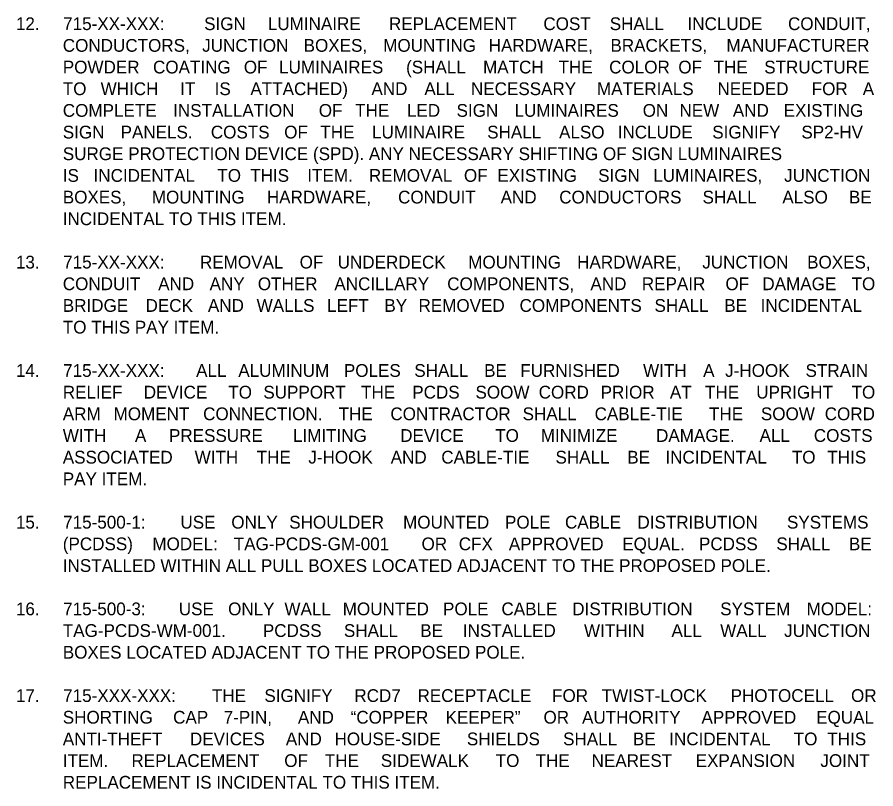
# Model space of a CAD drawing. Extents: x -55 to 2471539, y -90 to 3608906.
# Drawn here: x 543.9 to 1015.2, y 2948.6 to 3372.3 of the extents above; entities that cross this region are included whole.
import ezdxf

# ---------------------------------------------------------------- set-up
doc = ezdxf.new("R2010")
doc.units = 0
doc.layers.add('XSCell', color=7, linetype='Continuous')

msp = doc.modelspace()

# ---------------------------------------------------------------- texts
at = {"layer": 'XSCell'}
for s, p in [('12.', (543.22, 3365.2)), ('715-XX-XXX: ', (569.17, 3365.2)), ('SIGN ', (646.54, 3365.2)), ('LUMINAIRE ', (681.53, 3365.2)), ('REPLACEMENT ', (747.98, 3365.2)), ('COST ', (832.73, 3365.2)), ('SHALL ', (869.16, 3365.2)), ('INCLUDE ', (911.86, 3365.2)), ('CONDUIT, ', (967.01, 3365.2)), ('CONDUCTORS, ', (568.97, 3353.3)), ('JUNCTION ', (645.47, 3353.3)), ('BOXES, ', (701.16, 3353.3)), ('MOUNTING ', (744.83, 3353.3)), ('HARDWARE, ', (802.74, 3353.3)), ('BRACKETS, ', (869.55, 3353.3)), ('MANUFACTURER ', (933.2, 3353.3)), ('POWDER ', (568.97, 3341.4)), ('COATING ', (618.49, 3341.4)), ('OF ', (668.33, 3341.4)), ('LUMINAIRES ', (687.66, 3341.4)), ('(SHALL ', (757.39, 3341.4)), ('MATCH ', (799.64, 3341.4)), ('THE ', (841.03, 3341.4)), ('COLOR ', (868.85, 3341.4)), ('OF ', (906.81, 3341.4)), ('THE ', (926.14, 3341.4)), ('STRUCTURE ', (953.96, 3341.4)), ('ATTACHED) ', (671.94, 3329.5)), ('TO ', (568.97, 3329.5)), ('WHICH ', (589.74, 3329.5)), ('IT ', (633.36, 3329.5)), ('IS ', (652.3, 3329.5)), ('AND ', (738.36, 3329.5)), ('ALL ', (767.43, 3329.5)), ('NECESSARY ', (792.98, 3329.5)), ('MATERIALS ', (862.16, 3329.5)), ('NEEDED ', (928.29, 3329.5)), ('FOR ', (980.04, 3329.5)), ('A ', (1008.04, 3329.5)), ('COMPLETE ', (568.97, 3317.6)), ('INSTALLATION ', (629.54, 3317.6)), ('OF ', (709.47, 3317.6)), ('THE ', (729.42, 3317.6)), ('LED ', (757.86, 3317.6)), ('SIGN ', (785.1, 3317.6)), ('LUMINAIRES ', (816.92, 3317.6)), ('ON ', (887.26, 3317.6)), ('NEW ', (907.43, 3317.6)), ('AND ', (936.73, 3317.6)), ('EXISTING ', (964.63, 3317.6)), ('SIGN ', (568.97, 3305.7)), ('PANELS. ', (600.71, 3305.7)), ('COSTS ', (650.23, 3305.7)), ('OF ', (690.48, 3305.7)), ('THE ', (710.35, 3305.7)), ('LUMINAIRE ', (738.71, 3305.7)), ('SHALL ', (801.9, 3305.7)), ('ALSO ', (841.35, 3305.7)), ('INCLUDE ', (873.54, 3305.7)), ('SIGNIFY ', (925.43, 3305.7)), ('SP2-HV ', (974.35, 3305.7)), ('SURGE PROTECTION DEVICE (SPD). ANY NECESSARY SHIFTING OF SIGN LUMINAIRES ', (568.97, 3293.8)), ('IS ', (568.97, 3281.9)), ('INCIDENTAL ', (585.86, 3281.9)), ('TO ', (653.79, 3281.9)), ('THIS ', (671.82, 3281.9)), ('ITEM. ', (703.16, 3281.9)), ('REMOVAL ', (736.96, 3281.9)), ('OF ', (789.14, 3281.9)), ('EXISTING ', (807.51, 3281.9)), ('SIGN ', (862.81, 3281.9)), ('LUMINAIRES, ', (893.05, 3281.9)), ('JUNCTION ', (964.88, 3281.9)), ('BOXES, ', (568.97, 3270)), ('MOUNTING ', (617.84, 3270)), ('HARDWARE, ', (680.97, 3270)), ('CONDUIT ', (752.99, 3270)), ('AND ', (809.28, 3270)), ('CONDUCTORS ', (841.45, 3270)), ('SHALL ', (920.11, 3270)), ('ALSO ', (963.9, 3270)), ('BE ', (1000.44, 3270)), ('INCIDENTAL TO THIS ITEM.', (568.97, 3258.1)), ('13.', (543.22, 3234.3)), ('715-XX-XXX: ', (569.17, 3234.3)), ('REMOVAL ', (644.27, 3234.3)), ('OF ', (698.96, 3234.3)), ('UNDERDECK ', (719.83, 3234.3)), ('MOUNTING ', (791.49, 3234.3)), ('HARDWARE, ', (851.27, 3234.3)), ('JUNCTION ', (919.94, 3234.3)), ('BOXES, ', (977.5, 3234.3)), ('CONDUIT ', (568.97, 3222.4)), ('AND ', (621.32, 3222.4)), ('ANY ', (649.54, 3222.4)), ('OTHER ', (676.01, 3222.4)), ('ANCILLARY ', (718.01, 3222.4)), ('COMPONENTS, ', (779.96, 3222.4)), ('AND ', (858.56, 3222.4)), ('REPAIR ', (886.78, 3222.4)), ('OF ', (932.66, 3222.4)), ('DAMAGE ', (952.93, 3222.4)), ('TO ', (1001.9, 3222.4)), ('BRIDGE ', (568.97, 3210.5)), ('DECK ', (614.38, 3210.5)), ('AND ', (648.62, 3210.5)), ('WALLS ', (675.36, 3210.5)), ('LEFT ', (714.01, 3210.5)), ('BY ', (745.49, 3210.5)), ('REMOVED ', (764.2, 3210.5)), ('COMPONENTS ', (819.66, 3210.5)), ('SHALL ', (893.72, 3210.5)), ('BE ', (932.08, 3210.5)), ('INCIDENTAL ', (951.99, 3210.5)), ('TO THIS PAY ITEM.', (568.97, 3198.6)), ('14.', (543.22, 3174.8)), ('715-XX-XXX: ', (569.17, 3174.8)), ('ALL ', (642.14, 3174.8)), ('ALUMINUM ', (665.3, 3174.8)), ('POLES ', (723.25, 3174.8)), ('SHALL ', (761.9, 3174.8)), ('BE ', (800.21, 3174.8)), ('FURNISHED ', (820.07, 3174.8)), ('WITH ', (887.46, 3174.8)), ('A ', (920.44, 3174.8)), ('J-HOOK ', (932.51, 3174.8)), ('STRAIN ', (976.64, 3174.8)), ('RELIEF ', (568.97, 3162.9)), ('DEVICE ', (613.41, 3162.9)), ('TO ', (659.8, 3162.9)), ('SUPPORT ', (679.05, 3162.9)), ('THE ', (732.69, 3162.9)), ('PCDS ', (760.78, 3162.9)), ('SOOW ', (795.48, 3162.9)), ('CORD ', (830.16, 3162.9)), ('PRIOR ', (864.16, 3162.9)), ('AT ', (902.18, 3162.9)), ('THE ', (921.48, 3162.9)), ('UPRIGHT ', (949.56, 3162.9)), ('TO ', (1001.9, 3162.9)), ('ARM ', (568.97, 3151)), ('MOMENT ', (596.85, 3151)), ('CONNECTION. ', (645.98, 3151)), ('THE ', (720.32, 3151)), ('CONTRACTOR ', (748.76, 3151)), ('SHALL ', (821.34, 3151)), ('CABLE-TIE ', (860.87, 3151)), ('THE ', (923.67, 3151)), ('SOOW ', (952.12, 3151)), ('CORD ', (987.15, 3151)), ('WITH ', (568.97, 3139.1)), ('A ', (608.57, 3139.1)), ('PRESSURE ', (627.26, 3139.1)), ('LIMITING ', (695.29, 3139.1)), ('DEVICE ', (754.15, 3139.1)), ('TO ', (806.3, 3139.1)), ('MINIMIZE ', (831.32, 3139.1)), ('DAMAGE. ', (894.58, 3139.1)), ('ALL ', (951.4, 3139.1)), ('COSTS ', (981.18, 3139.1)), ('ASSOCIATED ', (568.97, 3127.2)), ('WITH ', (641.34, 3127.2)), ('THE ', (675.41, 3127.2)), ('J-HOOK ', (703.72, 3127.2)), ('AND ', (748.94, 3127.2)), ('CABLE-TIE ', (776.71, 3127.2)), ('SHALL ', (839.39, 3127.2)), ('BE ', (878.78, 3127.2)), ('INCIDENTAL ', (899.73, 3127.2)), ('TO ', (969.12, 3127.2)), ('THIS ', (988.6, 3127.2)), ('PAY ITEM.', (568.97, 3115.3)), ('15.', (543.22, 3091.5)), ('715-500-1: ', (569.17, 3091.5)), ('USE ', (633.53, 3091.5)), ('ONLY ', (661.46, 3091.5)), ('SHOULDER ', (693.26, 3091.5)), ('MOUNTED ', (755.74, 3091.5)), ('POLE ', (811.69, 3091.5)), ('CABLE ', (844.61, 3091.5)), ('DISTRIBUTION ', (884.36, 3091.5)), ('SYSTEMS ', (966.44, 3091.5)), ('(PCDSS) ', (568.97, 3079.6)), ('MODEL: ', (618.13, 3079.6)), ('TAG-PCDS-GM-001 ', (662.81, 3079.6)), ('OR ', (765.87, 3079.6)), ('CFX ', (786.3, 3079.6)), ('APPROVED ', (813.79, 3079.6)), ('EQUAL. ', (876.02, 3079.6)), ('PCDSS ', (918.14, 3079.6)), ('SHALL ', (960.6, 3079.6)), ('BE ', (1000.44, 3079.6)), ('INSTALLED WITHIN ALL PULL BOXES LOCATED ADJACENT TO THE PROPOSED POLE.', (568.97, 3067.7)), ('16.', (543.22, 3043.9)), ('715-500-3: ', (569.17, 3043.9)), ('USE ', (632.65, 3043.9)), ('ONLY ', (659.7, 3043.9)), ('WALL ', (690.61, 3043.9)), ('MOUNTED ', (722.61, 3043.9)), ('POLE ', (777.67, 3043.9)), ('CABLE ', (809.72, 3043.9)), ('DISTRIBUTION ', (848.58, 3043.9)), ('SYSTEM ', (929.79, 3043.9)), ('MODEL: ', (977.24, 3043.9)), ('TAG-PCDS-WM-001. ', (568.97, 3032)), ('PCDSS ', (678.77, 3032)), ('SHALL ', (723.26, 3032)), ('BE ', (765.14, 3032)), ('INSTALLED ', (788.57, 3032)), ('WITHIN ', (855.04, 3032)), ('ALL ', (903.06, 3032)), ('WALL ', (929.79, 3032)), ('JUNCTION ', (964.88, 3032)), ('BOXES LOCATED ADJACENT TO THE PROPOSED POLE.', (568.97, 3020.1)), ('17.', (543.22, 2996.3)), ('715-XXX-XXX: ', (569.17, 2996.3)), ('THE ', (650.77, 2996.3)), ('SIGNIFY ', (679.6, 2996.3)), ('RCD7 ', (728.99, 2996.3)), ('RECEPTACLE ', (763.66, 2996.3)), ('FOR ', (837.52, 2996.3)), ('TWIST-LOCK ', (864.74, 2996.3)), ('PHOTOCELL ', (935.51, 2996.3)), ('OR ', (1001.6, 2996.3)), ('SHORTING ', (568.97, 2984.4)), ('CAP ', (629.52, 2984.4)), ('7-PIN, ', (657.27, 2984.4)), ('AND ', (698.02, 2984.4)), ('“COPPER ', (726.96, 2984.4)), ('KEEPER” ', (779.08, 2984.4)), ('OR ', (832.81, 2984.4)), ('AUTHORITY ', (853.97, 2984.4)), ('APPROVED ', (919.52, 2984.4)), ('EQUAL ', (982.47, 2984.4)), ('ANTI-THEFT ', (568.97, 2972.5)), ('DEVICES ', (638.75, 2972.5)), ('AND ', (691.39, 2972.5)), ('HOUSE-SIDE ', (718.12, 2972.5)), ('SHIELDS ', (790.76, 2972.5)), ('SHALL ', (843.57, 2972.5)), ('BE ', (881.92, 2972.5)), ('INCIDENTAL ', (901.82, 2972.5)), ('TO ', (970.16, 2972.5)), ('THIS ', (988.6, 2972.5)), ('ITEM. ', (568.97, 2960.6)), ('REPLACEMENT ', (606.65, 2960.6)), ('OF ', (690.52, 2960.6)), ('THE ', (712.77, 2960.6)), ('SIDEWALK ', (743.51, 2960.6)), ('TO ', (806.57, 2960.6)), ('THE ', (828.47, 2960.6)), ('NEAREST ', (859.21, 2960.6)), ('EXPANSION ', (916.33, 2960.6)), ('JOINT ', (984.78, 2960.6)), ('REPLACEMENT IS INCIDENTAL TO THIS ITEM.', (568.97, 2948.7))]:
    msp.add_text(s, height=7, dxfattribs=at).set_placement(p)

doc.saveas('drawing.dxf')
